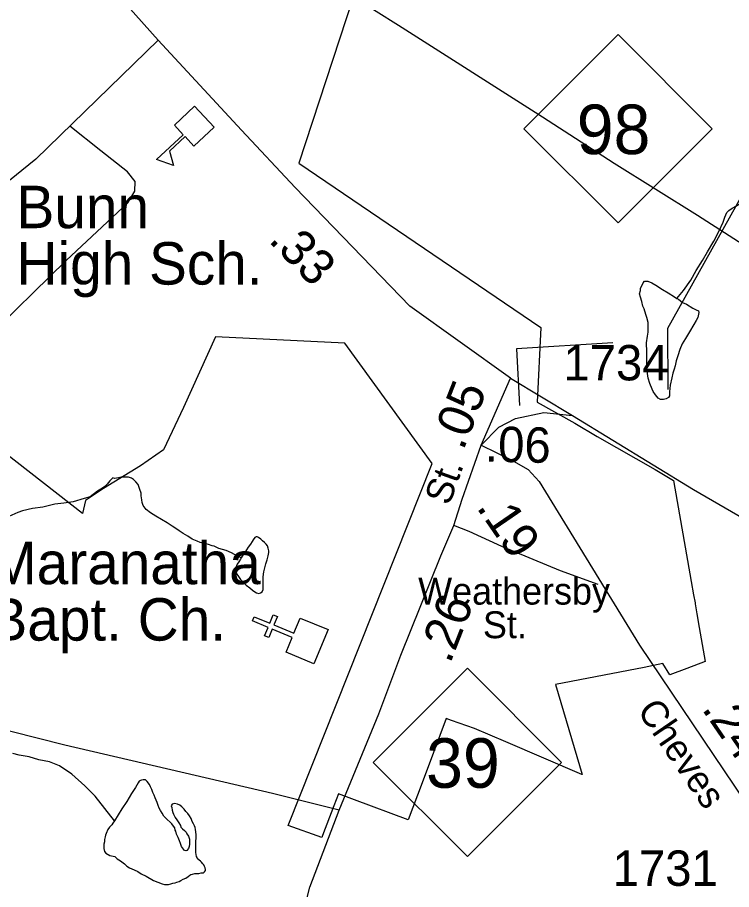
# Model space of a CAD drawing. Extents: x 2126262 to 2293712, y 749403 to 919119.
# Drawn here: x 2221728 to 2224251, y 800917 to 803998 of the extents above; entities that cross this region are included whole.
import ezdxf

# ---------------------------------------------------------------- set-up
doc = ezdxf.new("R2010")
doc.units = 0
for name, color, linetype in [('Exist Boundary Political City Limit New', 7, 'Continuous'), ('Exist Cultural Church CELL', 7, 'Continuous'), ('Exist Cultural Church Label', 7, 'Continuous'), ('Exist Cultural Educational Facility High CELL', 7, 'Continuous'), ('Exist Cultural Educational Facility High Label', 7, 'Continuous'), ('Exist Hydrographic Misc Water Feature', 7, 'Continuous'), ('Exist Railroad Mainline', 7, 'Continuous'), ('Exist Road Non-System Type 51', 7, 'Continuous'), ('Exist Road Non-System Type 51 Label', 7, 'Continuous'), ('Exist Road Primary NC Attributed', 7, 'Continuous'), ('Exist Road Primary NC Label', 7, 'Continuous'), ('Exist Road Primary NC Service Mileage Hundredths English Label', 7, 'Continuous'), ('Exist Road Primary NC Shield CELL', 7, 'Continuous'), ('Exist Road Primary NC Shield Number Label', 7, 'Continuous'), ('Exist Road Secondary Mileage Hundredths English Label', 7, 'Continuous'), ('Exist Road Secondary Type 51 Attributed', 7, 'Continuous'), ('Exist Road Secondary Type 51 Label', 7, 'Continuous'), ('Exist Road Secondary Type 51 Number Label', 7, 'Continuous'), ('Map Preparation Boundary City Limit Buffer Line', 7, 'Continuous')]:
    doc.layers.add(name, color=color, linetype=linetype)

msp = doc.modelspace()

# ---------------------------------------------------------------- linework, layer by layer
at = {"layer": 'Exist Boundary Political City Limit New'}
for points in [[(2223223.5, 805013.6), (2222722.5, 803482.6), (2223577.5, 802902.6), (2223564.8, 802639.4), (2223697.5, 802565.1), (2223776.2, 802517.6), (2223981.5, 802400.8), (2224046, 802362.7), (2224109, 802004.8), (2224117.2, 801957.8), (2224122, 801930.2), (2224122.8, 801926.3), (2224129, 801890.6), (2224137.2, 801842.6), (2224158.2, 801722.9), (2224093.2, 801698.4), (2224033.2, 801676.1), (2224008, 801715.2), (2223942, 801701), (2223629.5, 801641.4), (2223723.5, 801323.2), (2223722, 801323.1), (2223453.5, 801438.8), (2223343, 801486.4), (2223261.8, 801514.8), (2223243, 801521.2), (2223175.2, 801341.6), (2223141, 801251), (2223108, 801163.2), (2222918.5, 801234), (2222862.2, 801255.1)], [(2222862.2, 801255.1), (2222846, 801212.9), (2222806, 801108), (2222803.5, 801101.4), (2222684, 801143.5), (2223193, 802421.9), (2222884.5, 802847.1), (2222427.5, 802869.8), (2222314.8, 802620.4), (2222243.5, 802470.6), (2222162, 802414.2), (2222031.5, 802334.1), (2221967.8, 802291), (2221957.5, 802245), (2221339.2, 802726.8)]]:
    msp.add_lwpolyline(points, dxfattribs=at)
at = {"layer": 'Exist Cultural Church CELL'}
msp.add_lwpolyline([(2222676.8, 801755.4), (2222698.4, 801808), (2222628.1, 801837.1), (2222615.8, 801807.5), (2222601.1, 801813.6), (2222613.3, 801843.2), (2222557.7, 801866.2), (2222563.8, 801881), (2222619.4, 801858), (2222631.6, 801887.6), (2222646.4, 801881.5), (2222634.2, 801851.9), (2222704.5, 801822.8), (2222726.7, 801876.1), (2222825.1, 801835.4), (2222775.2, 801714.7)], close=True, dxfattribs=at)
at = {"layer": 'Exist Cultural Educational Facility High CELL'}
msp.add_lwpolyline([(2222423.1, 803609.9), (2222351.5, 803543.2), (2222320.1, 803576.8), (2222265.2, 803525.6), (2222279.5, 803474.7), (2222219.5, 803496.2), (2222313.5, 803583.8), (2222282.1, 803617.5), (2222353.8, 803684.3)], close=True, dxfattribs=at)
at = {"layer": 'Exist Hydrographic Misc Water Feature'}
for points in [[(2224057.6, 803004.9), (2224081.4, 803033.1), (2224107.1, 803069.3), (2224126.7, 803103.5), (2224148.5, 803139.6), (2224166.3, 803169.7), (2224188.1, 803207.9), (2224205.7, 803242), (2224221.5, 803274.2), (2224227.2, 803292.2), (2224235, 803308.3), (2224241, 803316.3), (2224253.1, 803324.4), (2224269.1, 803332.5), (2224286.7, 803344.6), (2224300.6, 803354.8), (2224314.8, 803362.9), (2224326.5, 803373), (2224344.5, 803385.1), (2224352.5, 803391.2), (2224360.3, 803399.2), (2224370.1, 803407.3), (2224380.2, 803419.4)], [(2224027.5, 802683.6), (2224026.5, 802900), (2224288.5, 803370.3)], [(2224057.6, 803004.9), (2224063.8, 803003), (2224077.7, 802991.1), (2224091.7, 802985.2), (2224114, 802971.4), (2224125.9, 802965.5), (2224133.9, 802961.6), (2224136, 802955.6), (2224132.3, 802937.5), (2224126.1, 802927.5), (2224118.1, 802913.5), (2224102.5, 802887.3), (2224088.8, 802863.2), (2224076.9, 802845.1), (2224068.9, 802825.1), (2224061.1, 802803.1), (2224055.4, 802785), (2224051.5, 802767), (2224047.8, 802754.9), (2224043.7, 802740.9), (2224040, 802724.9), (2224034.3, 802698.8), (2224032.2, 802674.8), (2224032.4, 802664.8), (2224032.4, 802660.8), (2224028.5, 802654.8), (2224020.5, 802650.8), (2224010.5, 802648.6), (2224000.4, 802648.6), (2223992.4, 802652.5), (2223982.4, 802664.5), (2223974.2, 802676.3), (2223970.3, 802684.3), (2223962.3, 802704.3), (2223955.9, 802724.2), (2223953.7, 802740.2), (2223951.6, 802762.1), (2223951.4, 802776.1), (2223951.4, 802794.2), (2223951.2, 802816.2), (2223951, 802848.1), (2223954.7, 802872.2), (2223956.8, 802886.1), (2223956.6, 802906.1), (2223956.6, 802920.1), (2223952.2, 802938.1), (2223948.1, 802948), (2223942, 802968), (2223937.9, 802978), (2223933.8, 802993.9), (2223929.7, 803009.9), (2223925.4, 803021.8), (2223929.5, 803033.8), (2223929.5, 803039.8), (2223939.1, 803059.9), (2223943.2, 803066), (2223955.1, 803066.1), (2223969.3, 803060.2), (2223983.2, 803052.3), (2224007.4, 803036.6), (2224027.5, 803024.7), (2224049.4, 803010.9), (2224057.6, 803004.9)], [(2222517.7, 802088.7), (2222505.6, 802094.6), (2222483.5, 802106.4), (2222465.4, 802114.3), (2222439.4, 802122.1), (2222423.4, 802130), (2222415.4, 802131.9), (2222403.3, 802135.8), (2222387.3, 802139.7), (2222373.1, 802143.5), (2222363.3, 802147.4), (2222345.3, 802155.3), (2222329.3, 802165.1), (2222312.9, 802175), (2222298.9, 802184.9), (2222287, 802192.8), (2222274.9, 802200.7), (2222256.7, 802212.5), (2222236.8, 802224.4), (2222216.5, 802236.2), (2222198.4, 802248.1), (2222182.6, 802260), (2222172.4, 802274), (2222168.5, 802283.9), (2222166.7, 802294), (2222164.4, 802308), (2222164.4, 802317.9), (2222160.3, 802329.9), (2222154.1, 802347.9), (2222146.4, 802357.8), (2222138.1, 802365.8), (2222130.2, 802369.8), (2222120.1, 802373.8), (2222114.2, 802373.7), (2222102.5, 802373.6), (2222094.5, 802373.6), (2222084.4, 802371.5), (2222070.5, 802369.4), (2222064.5, 802371.3)], [(2222064.5, 802371.3), (2222054.7, 802361.3), (2222044.6, 802349.2), (2222036.6, 802341.1), (2222022.9, 802331.1), (2222011, 802325), (2221985, 802304.8), (2221963.2, 802298.7), (2221925.1, 802286.4), (2221891.3, 802282.2), (2221859.3, 802278), (2221817.4, 802267.7), (2221781.4, 802263.5), (2221745.5, 802255.2), (2221729.5, 802249.1), (2221697.7, 802234.9)], [(2222517.7, 802088.7), (2222515.7, 802084.7), (2222509.7, 802074.7), (2222504, 802066.6), (2222499.9, 802054.6), (2222498, 802044.6), (2222500.3, 802034.6), (2222508.3, 802022.6), (2222516.3, 802012.7), (2222536.4, 801992.9), (2222548.5, 801983), (2222558.5, 801975.1), (2222566.7, 801969.2), (2222572.7, 801965.2), (2222580.7, 801963.3), (2222586.6, 801965.3), (2222592.7, 801969.4), (2222596.4, 801977.4), (2222596.4, 801991.4), (2222596.2, 802003.4), (2222596.2, 802021.4), (2222597.9, 802039.4), (2222602, 802053.4), (2222605.7, 802067.5), (2222609.8, 802081.5), (2222613.5, 802095.5), (2222615.5, 802107.5), (2222615.5, 802113.5), (2222613.5, 802123.5), (2222611.2, 802131.5), (2222607.1, 802137.5), (2222601.2, 802143.4), (2222593.2, 802149.3), (2222587.2, 802155.3), (2222579, 802161.2), (2222574.9, 802163.1), (2222571, 802163.1), (2222566.9, 802161.1), (2222561.2, 802153), (2222557.3, 802147), (2222551.1, 802136.9), (2222543.5, 802126.9), (2222537.4, 802116.9), (2222533.5, 802110.8), (2222527.5, 802102.7), (2222521.6, 802094.7), (2222517.7, 802088.7)], [(2222070.9, 801159.8), (2222002.2, 801247.3), (2221965.9, 801283.1), (2221919.8, 801324.8), (2221875.7, 801354.5), (2221841.4, 801368.2), (2221803.5, 801375.9), (2221769.5, 801385.7), (2221733.4, 801391.4), (2221711.4, 801397.3)], [(2222289.7, 801113.2), (2222287.6, 801123.2), (2222285.4, 801127.2), (2222283.5, 801135.2), (2222279.4, 801141.2), (2222273.5, 801149), (2222267.5, 801155), (2222257.3, 801164.9), (2222245.2, 801176.8), (2222239.2, 801186.8), (2222232.9, 801196.7), (2222229, 801204.7), (2222224.9, 801214.6), (2222220.8, 801224.6), (2222214.6, 801240.7), (2222210.7, 801250.6), (2222206.4, 801260.5), (2222202.5, 801270.5), (2222198.4, 801280.4), (2222194.1, 801288.4), (2222186.1, 801298.3), (2222180.2, 801304.3), (2222176.3, 801304.2), (2222172.2, 801304.2), (2222166.2, 801304.1), (2222162.1, 801302.1), (2222158.2, 801300.1), (2222154.1, 801294.1), (2222144.5, 801278), (2222130.4, 801256.1), (2222114.4, 801228), (2222096.5, 801202), (2222070.9, 801159.8)], [(2222071.7, 801033.9), (2222079.7, 801026), (2222085.7, 801022), (2222091.6, 801018.1), (2222106, 801008.1), (2222114, 801000.2), (2222124.2, 800994.2), (2222132.2, 800990.3), (2222140.2, 800986.3), (2222152.5, 800980.3), (2222164.6, 800972.4), (2222182.6, 800964.5), (2222208.9, 800948.6), (2222223.2, 800942.8), (2222239.2, 800936.9), (2222247.2, 800934.9), (2222253.2, 800935), (2222261.2, 800935.1), (2222269.2, 800937.1), (2222277.2, 800939.2), (2222285.2, 800941.3), (2222290.9, 800943.3), (2222298.9, 800945.4), (2222304.9, 800949.4), (2222312.9, 800953.4), (2222322.9, 800957.6), (2222330.9, 800963.6), (2222336.8, 800967.6), (2222340.9, 800969.7), (2222346.7, 800971.7), (2222354.7, 800973.8), (2222360.6, 800973.8), (2222368.6, 800973.9), (2222376.6, 800976), (2222384.6, 800976.1), (2222388.7, 800980.1), (2222392.6, 800984.1), (2222392.6, 800988.1), (2222390.8, 800994.1), (2222388.7, 800998.1), (2222386.5, 801004.1), (2222382.4, 801008), (2222378.5, 801013.9), (2222374.4, 801017.9), (2222364.5, 801025.9), (2222362.5, 801029.8), (2222360.2, 801033.8), (2222358.2, 801047.8), (2222358.2, 801059.8), (2222358, 801065.8), (2222358, 801071.7), (2222358, 801077.7), (2222358, 801089.7), (2222359.6, 801097.8), (2222359.6, 801105.7), (2222359.6, 801111.8), (2222357.3, 801129.8), (2222355.5, 801135.8), (2222353.5, 801141.7), (2222349.4, 801149.7), (2222345.3, 801157.6), (2222341.2, 801167.7), (2222335.2, 801177.6), (2222329.3, 801185.5), (2222322.9, 801193.4), (2222317, 801201.4), (2222309, 801209.3), (2222301, 801215.3), (2222292.8, 801219.2), (2222282.7, 801221.1), (2222274.9, 801219.1), (2222271, 801213), (2222272.9, 801207.1), (2222274.9, 801197.1), (2222277, 801189.1), (2222279.2, 801183.1), (2222285.2, 801171.1), (2222291.1, 801163.2), (2222297.5, 801153.3), (2222303.4, 801143.3), (2222305.5, 801137.3), (2222311.4, 801131.4), (2222317.4, 801125.5), (2222323.7, 801119.5), (2222325.8, 801113.5), (2222331.7, 801105.6), (2222335.6, 801095.6), (2222336, 801087.6), (2222336, 801077.6), (2222334, 801069.6), (2222332.1, 801061.6), (2222326.2, 801055.5), (2222322.3, 801053.5), (2222318.2, 801055.4), (2222314.1, 801059.4), (2222307.9, 801069.4), (2222304, 801079.3), (2222299.9, 801089.3), (2222295.6, 801101.3), (2222289.7, 801113.2)], [(2222070.9, 801159.8), (2222064.9, 801151.8), (2222060.8, 801145.8), (2222052.8, 801137.8), (2222047.1, 801129.7), (2222041.2, 801115.6), (2222039.1, 801109.6), (2222037.3, 801103.6), (2222035.4, 801093.6), (2222035.4, 801085.6), (2222033.4, 801077.6), (2222033.4, 801071.6), (2222033.4, 801061.6), (2222035.6, 801051.7), (2222039.7, 801045.7), (2222053.7, 801037.8), (2222071.7, 801033.9)]]:
    msp.add_lwpolyline(points, dxfattribs=at)
at = {"layer": 'Exist Railroad Mainline'}
msp.add_lwpolyline([(2222265.6, 804436.9), (2222334.9, 804408.6), (2222439.4, 804355.5), (2222565.8, 804292.5), (2222758.7, 804170.1), (2223074.1, 803970.9), (2223582.7, 803647), (2223835.9, 803483.2), (2224131.2, 803299.8), (2224466.9, 803084.5)], dxfattribs=at)
at = {"layer": 'Exist Road Non-System Type 51'}
msp.add_line((2223366.3, 802487.5), (2223470.4, 802723.7), dxfattribs=at)
for points in [[(2221091.3, 803036.9), (2221201.2, 802948.5), (2221357.5, 802840.9), (2221413.3, 802814.4), (2221477.5, 802803.2), (2221533.3, 802808.8), (2221607.3, 802854.9), (2221899.8, 803139.5), (2222118.1, 803342.8), (2222142.2, 803383.9), (2222143.6, 803418.8), (2222117.1, 803453), (2222022.9, 803526.4), (2221912.5, 803614.4)], [(2223779.4, 801995.3), (2223646.8, 802042.9), (2223439.6, 802128.8), (2223323.8, 802181.9), (2223269.4, 802202.9)], [(2222864.4, 801197.3), (2222629.4, 801256.1), (2221894.6, 801427.2), (2221516.4, 801522.2), (2220541.6, 801772.9), (2220222.6, 801849)]]:
    msp.add_lwpolyline(points, dxfattribs=at)
at = {"layer": 'Exist Road Primary NC Attributed'}
for points in [[(2222224.4, 803918.1), (2222116.8, 804039.3), (2221799.3, 804410.2), (2221642.6, 804574.9), (2221594.4, 804634.3), (2221422.6, 804826.4), (2220958.2, 805331.4), (2220853.1, 805451)], [(2223470.4, 802723.7), (2223113.8, 802978.2), (2222709.2, 803397.6), (2222519.4, 803600.1), (2222224.4, 803918.1)], [(2223366.3, 802487.5), (2223470.4, 802723.7)], [(2223470.4, 802723.7), (2223688.7, 802591.3)], [(2223688.7, 802591.3), (2224116.4, 802330.8), (2224623.7, 802036.8), (2225964.8, 801248.4)], [(2222714.4, 800745.5), (2222761.1, 800925), (2222864.4, 801197.3), (2223004.6, 801537.4), (2223082.8, 801745.5), (2223223.6, 802096.4), (2223269.4, 802202.9), (2223299, 802296.2), (2223366.3, 802487.5)]]:
    msp.add_lwpolyline(points, dxfattribs=at)
at = {"layer": 'Exist Road Primary NC Shield CELL'}
for points in [[(2223517, 803604.8), (2223850, 803937.8), (2224182.9, 803604.8), (2223850, 803271.8)], [(2222984.6, 801366.3), (2223317.6, 801699.3), (2223650.6, 801366.3), (2223317.6, 801033.3)]]:
    msp.add_lwpolyline(points, close=True, dxfattribs=at)
at = {"layer": 'Exist Road Secondary Type 51 Attributed'}
for points in [[(2222224.4, 803918.1), (2221793.2, 803497.8), (2221674.6, 803401.4), (2220828.2, 802875.6), (2220678.9, 802756.8), (2220609.8, 802683.5), (2220519.1, 802562), (2220424.2, 802387.4), (2220291, 802057.1), (2220222.6, 801849), (2220113, 801546.6), (2220016.8, 801344.1), (2219938.6, 801205.9), (2219479.5, 800587.2), (2219250, 800286.2), (2219139.7, 800132.6), (2219014.8, 799907), (2218850.7, 799594.6)], [(2223366.3, 802487.5), (2223428.5, 802550.5), (2223487.1, 802581.2), (2223587.6, 802602.2), (2223688.7, 802591.3)], [(2223366.3, 802487.5), (2223472.6, 802435.5), (2223532.6, 802401.1), (2223570.9, 802358.9), (2223925.8, 801780.5), (2224485.1, 800950.6), (2224583.4, 800824.2), (2224695.7, 800700.4)]]:
    msp.add_lwpolyline(points, dxfattribs=at)
at = {"layer": 'Exist Road Secondary Type 51 Label'}
msp.add_lwpolyline([(2223831.5, 802848.3), (2223491.3, 802826.7), (2223502.1, 802626.7)], dxfattribs=at)
at = {"layer": 'Map Preparation Boundary City Limit Buffer Line'}
for points in [[(2223223.5, 805013.6), (2222722.5, 803482.6), (2223577.5, 802902.6), (2223564.8, 802639.4), (2223697.5, 802565.1), (2223776.2, 802517.6), (2223981.5, 802400.8), (2224046, 802362.7), (2224109, 802004.8), (2224117.2, 801957.8), (2224122, 801930.2), (2224122.8, 801926.3), (2224129, 801890.6), (2224137.2, 801842.6), (2224158.2, 801722.9), (2224093.2, 801698.4), (2224033.2, 801676.1), (2224008, 801715.2), (2223942, 801701), (2223629.5, 801641.4), (2223723.5, 801323.2), (2223722, 801323.1), (2223453.5, 801438.8), (2223343, 801486.4), (2223261.8, 801514.8), (2223243, 801521.2), (2223175.2, 801341.6), (2223141, 801251), (2223108, 801163.2), (2222918.5, 801234), (2222862.2, 801255.1)], [(2222862.2, 801255.1), (2222846, 801212.9), (2222806, 801108), (2222803.5, 801101.4), (2222684, 801143.5), (2223193, 802421.9), (2222884.5, 802847.1), (2222427.5, 802869.8), (2222314.8, 802620.4), (2222243.5, 802470.6), (2222162, 802414.2), (2222031.5, 802334.1), (2221967.8, 802291), (2221957.5, 802245), (2221339.2, 802726.8)]]:
    msp.add_lwpolyline(points, dxfattribs=at)

# ---------------------------------------------------------------- texts
at = {"layer": 'Exist Cultural Church Label'}
for s, p in [('Maranatha', (2221628.6, 801995.7)), ('Bapt. Ch.', (2221628.6, 801796.5))]:
    msp.add_text(s, height=150, dxfattribs=at).set_placement(p)
at = {"layer": 'Exist Cultural Educational Facility High Label'}
for s, p in [('Bunn', (2221724.3, 803253.5)), ('High Sch.', (2221724.3, 803054.2))]:
    msp.add_text(s, height=150, dxfattribs=at).set_placement(p)
at = {"layer": 'Exist Road Non-System Type 51 Label'}
for s, p in [('Weathersby', (2223143.8, 801923.7)), ('St.', (2223372.6, 801805))]:
    msp.add_text(s, height=95, dxfattribs=at).set_placement(p)
at = {"layer": 'Exist Road Primary NC Label'}
msp.add_text('St.', height=95, rotation=70.3772, dxfattribs=at).set_placement((2223253.6, 802270.4))
at = {"layer": 'Exist Road Primary NC Service Mileage Hundredths English Label'}
for s, rotation, p in [('.33', 313.9707, (2222611.9, 803208.5)), ('.05', 68.6505, (2223303, 802465.2)), ('.26', 68.6505, (2223256.5, 801712))]:
    msp.add_text(s, height=125, rotation=rotation, dxfattribs=at).set_placement(p)
at = {"layer": 'Exist Road Primary NC Shield Number Label'}
for s, p in [('98', (2223704.1, 803515.1)), ('39', (2223171.8, 801276.6))]:
    msp.add_text(s, height=175, dxfattribs=at).set_placement(p)
at = {"layer": 'Exist Road Secondary Mileage Hundredths English Label'}
for s, rotation, p in [('.06', 358.7857, (2223378.7, 802428.9)), ('.19', 304.4874, (2223347.5, 802267.3)), ('.24', 304.4874, (2224143.5, 801555.5))]:
    msp.add_text(s, height=125, rotation=rotation, dxfattribs=at).set_placement(p)
at = {"layer": 'Exist Road Secondary Type 51 Label'}
msp.add_text('Cheves', height=95, rotation=304.3651, dxfattribs=at).set_placement((2223915.1, 801549.6))
at = {"layer": 'Exist Road Secondary Type 51 Number Label'}
for s, p in [('1734', (2223656.7, 802715.8)), ('1731', (2223830.8, 800930.2))]:
    msp.add_text(s, height=125, dxfattribs=at).set_placement(p)

doc.saveas('drawing.dxf')
